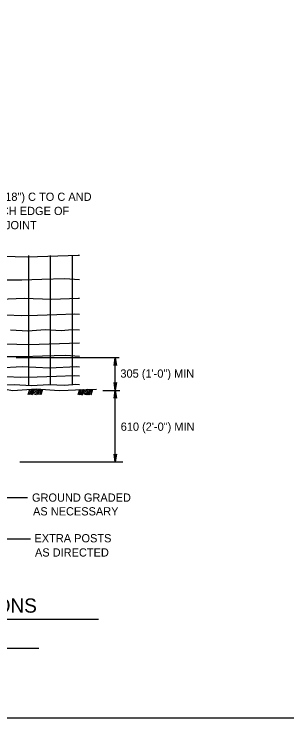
# Model space of a CAD drawing. Extents: x 13 to 918, y -903 to 879.
# Drawn here: x 474.8 to 578.5, y -294.1 to -26.6 of the extents above; entities that cross this region are included whole.
import ezdxf

# ---------------------------------------------------------------- set-up
doc = ezdxf.new("R2010")
doc.units = 0
for name, color, linetype in [('1', 7, 'Continuous'), ('2', 7, 'Continuous'), ('3', 7, 'Continuous')]:
    doc.layers.add(name, color=color, linetype=linetype)

msp = doc.modelspace()

# ---------------------------------------------------------------- linework, layer by layer
at = {"layer": '1'}
for p, q in [((480.6605, -169.20375), (479.9585, -171.22875)), ((481.20225, -169.20375), (480.48775, -171.26625)), ((481.744, -169.20375), (481.02925, -171.26625)), ((482.2855, -169.20375), (481.571, -171.26625)), ((481.823, -171.26625), (481.598, -171.187)), ((483.3085, -171.237), (481.76475, -170.70375)), ((483.47725, -170.75375), (481.9335, -170.2205)), ((483.644, -170.2705), (482.10225, -169.735)), ((483.8105, -169.787), (482.269, -169.25375)), ((483.996, -169.20375), (483.2815, -171.26625)), ((483.97725, -169.30375), (483.69175, -169.20375)), ((484.53775, -169.20375), (483.823, -171.26625)), ((485.07725, -169.20375), (484.36475, -171.26625)), ((485.621, -169.20375), (484.9065, -171.26625)), ((499.65025, -169.28075), (498.948, -171.30575)), ((500.19175, -169.28075), (499.47725, -171.34325)), ((500.7335, -169.28075), (500.019, -171.34325)), ((501.27525, -169.28075), (500.5605, -171.34325)), ((502.298, -171.31425), (500.75425, -170.78075)), ((502.46675, -170.83075), (500.923, -170.2975)), ((502.6335, -170.3475), (501.09175, -169.812)), ((502.80025, -169.86425), (501.2585, -169.33075)), ((502.9855, -169.28075), (502.271, -171.34325)), ((502.96675, -169.38075), (502.6815, -169.28075)), ((503.52725, -169.28075), (502.81275, -171.34325)), ((504.06675, -169.28075), (503.35425, -171.34325)), ((504.6105, -169.28075), (503.896, -171.34325)), ((500.81275, -171.34325), (500.58775, -171.26425))]:
    msp.add_line(p, q, dxfattribs=at)
msp.add_lwpolyline([(838.2505, -294.06975), (838.2505, 269.93025), (52.2505, 269.93025), (52.2505, -294.06975), (838.2505, -294.06975), (838.2505, -267.71075), (638.2505, -267.71075), (638.2505, -203.03325), (838.2505, -203.03325), (838.2505, -174.06975), (638.2505, -174.06975), (638.2505, -294.06975), (717.052, -294.06975), (717.052, -267.71075), (717.052, -294.06975), (794.052, -294.06975), (794.052, -267.71075), (794.052, -280.02725), (838.2505, -280.02725)], dxfattribs=at)
at = {"layer": '2'}
for p, q in [((480.17925, -118.262), (480.17925, -167.562)), ((488.5105, -118.262), (488.5105, -167.562)), ((496.844, -118.262), (496.844, -167.562)), ((475.48975, -157.083), (514.773, -157.083)), ((513.25425, -169.583), (513.25425, -157.083)), ((508.53975, -169.583), (515.023, -169.583)), ((513.25425, -196.758), (513.25425, -169.583)), ((476.9855, -196.758), (516.0585, -196.758)), ((467.82525, -210.287), (479.844, -210.287)), ((464.27925, -225.9975), (481.01475, -225.9975))]:
    msp.add_line(p, q, dxfattribs=at)
for points in [[(370.80425, -118.54125), (372.36675, -118.54125), (377.9835, -118.45375), (383.373, -118.358), (388.76475, -118.81825), (399.8315, -118.358), (415.1585, -118.7225), (432.269, -118.358), (442.7605, -118.81825), (461.0605, -118.262), (479.83775, -118.81825), (499.15425, -118.16625), (499.57525, -118.185)], [(371.821, -127.3955), (371.821, -127.3955), (377.61675, -127.3955), (383.63975, -127.2245), (389.12525, -127.685), (396.1085, -127.2995), (402.15025, -127.58925), (408.173, -127.2995), (414.96275, -127.685), (423.97925, -127.12875), (430.11675, -127.58925), (437.53975, -127.2245), (443.773, -127.49325), (451.946, -127.49325), (457.719, -127.2995), (464.31675, -127.033), (471.87525, -127.608), (477.72525, -127.512), (485.26475, -127.33925), (494.08775, -127.05175), (499.57525, -127.39125)], [(372.12925, -134.687), (372.32525, -134.67675), (377.11675, -134.98075), (382.046, -134.5975), (387.80225, -134.50175), (393.00025, -134.78925), (399.13775, -134.50175), (405.46675, -134.885), (412.52725, -134.50175), (419.77725, -134.885), (427.5835, -134.50175), (435.6605, -134.885), (444.21475, -134.50175), (453.97925, -134.885), (461.86275, -134.4245), (469.4585, -134.962), (478.569, -134.50175), (488.9855, -134.962), (499.2085, -134.50175), (499.57525, -134.52675)], [(372.43775, -140.937), (372.47925, -140.92675), (377.42525, -140.7495), (383.8315, -141.037), (391.0815, -140.6725), (397.5855, -141.037), (403.5315, -140.7495), (409.30425, -140.7495), (415.15425, -141.22875), (421.46675, -140.94125), (427.70025, -140.6725), (433.55025, -141.22875), (440.6085, -141.133), (449.2605, -140.57675), (457.98775, -140.6725), (466.17925, -141.133), (472.048, -140.86425), (477.43775, -141.15175), (483.65225, -141.05575), (491.00025, -140.787), (497.78975, -140.4995), (499.57525, -140.60575)], [(473.42925, -146.558), (480.0085, -146.90175), (486.58775, -146.48075), (492.7065, -146.8245), (496.79175, -146.40375), (499.57525, -146.58075)], [(373.05225, -151.833), (372.97925, -151.86425), (378.596, -151.77675), (383.9855, -151.68075), (389.37725, -152.14125), (400.444, -151.68075), (415.771, -152.0455), (432.8815, -151.68075), (443.373, -152.14125), (461.673, -151.585), (480.45025, -152.14125), (499.57525, -151.4975)], [(372.15025, -156.5725), (372.0585, -156.55175), (377.92525, -156.55175), (383.948, -156.38075), (389.4335, -156.84125), (396.41675, -156.45575), (402.4585, -156.7455), (408.4815, -156.45575), (415.271, -156.84125), (424.28775, -156.285), (430.42525, -156.7455), (437.848, -156.38075), (444.0815, -156.6495), (452.25425, -156.6495), (458.02725, -156.45575), (464.62525, -156.18925), (472.1835, -156.76425), (478.0335, -156.66825), (485.573, -156.4955), (494.396, -156.208), (499.57525, -156.52875)], [(371.821, -160.72875), (371.596, -160.71825), (376.38775, -161.0225), (381.31675, -160.63925), (387.073, -160.54325), (392.271, -160.83075), (398.4085, -160.54325), (404.73775, -160.92675), (411.798, -160.54325), (419.048, -160.92675), (426.85425, -160.54325), (434.9315, -160.92675), (443.4855, -160.54325), (453.25025, -160.92675), (461.1335, -160.46625), (468.72925, -161.00375), (477.83975, -160.54325), (488.2565, -161.00375), (498.47925, -160.54325), (499.57525, -160.61625)], [(372.12925, -164.3745), (372.32525, -164.36425), (377.271, -164.187), (383.67725, -164.4745), (390.92725, -164.11), (397.4315, -164.4745), (403.37725, -164.187), (409.15025, -164.187), (415.00025, -164.66625), (421.31275, -164.37875), (427.546, -164.11), (433.396, -164.66625), (440.45425, -164.5705), (449.1065, -164.01425), (457.8335, -164.11), (466.02525, -164.5705), (471.894, -164.30175), (477.2835, -164.58925), (483.498, -164.49325), (490.846, -164.2245), (497.6355, -163.937), (499.57525, -164.05175)], [(467.7335, -167.60175), (474.81275, -167.39125), (481.39175, -167.735), (487.971, -167.31425), (494.08975, -167.658), (498.17525, -167.237), (499.57525, -167.32675)], [(470.17725, -169.1725), (471.41675, -169.15575), (474.25025, -169.583), (483.15425, -169.0205), (491.9605, -169.583), (495.31675, -169.44325), (498.1355, -169.3475), (506.10225, -169.10575)]]:
    msp.add_lwpolyline(points, dxfattribs=at)
at = {"layer": '3'}
for p, q in [((337.57525, -256.52675), (506.8315, -256.52675)), ((359.519, -267.51225), (484.1145, -267.51225))]:
    msp.add_line(p, q, dxfattribs=at)
for points in [[(512.898, -159.9205), (513.10425, -159.81425), (513.25425, -157.083), (512.898, -159.9205), (512.773, -160.06625), (513.25425, -157.083), (513.38975, -159.812), (513.59175, -159.912), (513.25425, -157.083), (513.72925, -160.06625), (513.59175, -159.912)], [(513.6105, -166.7455), (513.40425, -166.85175), (513.25425, -169.583), (513.6105, -166.7455), (513.7355, -166.5995), (513.25425, -169.583), (513.119, -166.85375), (512.91675, -166.75375), (513.25425, -169.583), (512.77925, -166.5995), (512.91675, -166.75375)], [(512.898, -172.4205), (513.10425, -172.31425), (513.25425, -169.583), (512.898, -172.4205), (512.773, -172.56625), (513.25425, -169.583), (513.38975, -172.312), (513.59175, -172.412), (513.25425, -169.583), (513.72925, -172.56625), (513.59175, -172.412)], [(513.6105, -193.9205), (513.40425, -194.02675), (513.25425, -196.758), (513.6105, -193.9205), (513.7355, -193.7745), (513.25425, -196.758), (513.119, -194.02875), (512.91675, -193.92875), (513.25425, -196.758), (512.77925, -193.7745), (512.91675, -193.92875)]]:
    msp.add_lwpolyline(points, dxfattribs=at)

# ---------------------------------------------------------------- texts
for s, height, p in [('FASTENERS AT 450 (18") C TO C AND', 3.1249995, (429.12725, -97.5495)), ('STAGGERED ON EACH EDGE OF', 3.1249995, (429.319, -102.93925)), ('FABRIC ALONG THE JOINT', 3.1249995, (429.51275, -108.33075)), ('305 (1\'-0") MIN', 3.1249995, (515.1885, -164.74325)), ('610 (2\'-0") MIN', 3.1249995, (515.298, -184.9365)), ('GROUND GRADED', 3.1249995, (481.569, -211.88925)), ('AS NECESSARY', 3.1249995, (481.95425, -217.11)), ('EXTRA POSTS', 3.1249995, (482.5105, -227.333)), ('AS DIRECTED', 3.1249995, (482.70225, -232.74125)), ('TREATMENT AT GROUND DEPRESSIONS', 5.4020865, (339.7315, -254.066))]:
    msp.add_text(s, height=height, dxfattribs=at).set_placement(p)

doc.saveas('drawing.dxf')
